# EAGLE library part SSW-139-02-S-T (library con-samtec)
THROUGH-HOLE .025" SQ POST SOCKET Source: Samtec SSW.pdf
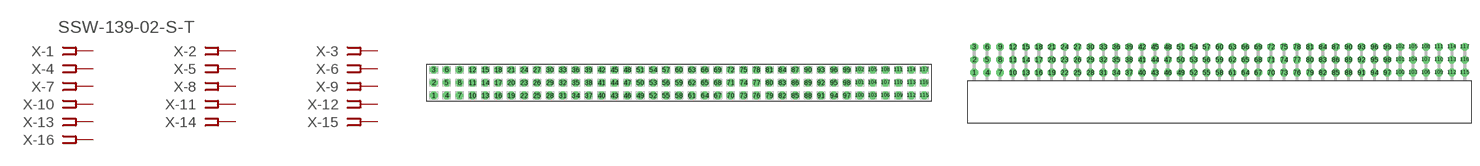
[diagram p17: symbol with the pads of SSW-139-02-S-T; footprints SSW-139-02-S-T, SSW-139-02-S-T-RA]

Designator prefix X; gates -1=FPINV -2=FPIN -3=FPIN -4=FPIN -5=FPIN -6=FPIN -7=FPIN -8=FPIN -9=FPIN -10=FPIN -11=FPIN -12=FPIN -13=FPIN -14=FPIN -15=FPIN -16=FPIN -17=FPIN -18=FPIN -19=FPIN -20=FPIN -21=FPIN -22=FPIN -23=FPIN -24=FPIN -25=FPIN -26=FPIN -27=FPIN -28=FPIN -29=FPIN -30=FPIN -31=FPIN -32=FPIN -33=FPIN -34=FPIN -35=FPIN -36=FPIN -37=FPIN -38=FPIN -39=FPIN -40=FPIN -41=FPIN -42=FPIN -43=FPIN -44=FPIN -45=FPIN -46=FPIN -47=FPIN -48=FPIN -49=FPIN -50=FPIN -51=FPIN -52=FPIN -53=FPIN -54=FPIN -55=FPIN -56=FPIN -57=FPIN -58=FPIN -59=FPIN -60=FPIN -61=FPIN -62=FPIN -63=FPIN -64=FPIN -65=FPIN -66=FPIN -67=FPIN -68=FPIN -69=FPIN -70=FPIN -71=FPIN -72=FPIN -73=FPIN -74=FPIN -75=FPIN -76=FPIN -77=FPIN -78=FPIN -79=FPIN -80=FPIN -81=FPIN -82=FPIN -83=FPIN -84=FPIN -85=FPIN -86=FPIN -87=FPIN -88=FPIN -89=FPIN -90=FPIN -91=FPIN -92=FPIN -93=FPIN -94=FPIN -95=FPIN -96=FPIN -97=FPIN -98=FPIN -99=FPIN -100=FPIN -101=FPIN -102=FPIN -103=FPIN -104=FPIN -105=FPIN -106=FPIN -107=FPIN -108=FPIN -109=FPIN -110=FPIN -111=FPIN -112=FPIN -113=FPIN -114=FPIN -115=FPIN -116=FPIN -117=FPIN

## SSW-139-02-S-T (OC_FARNELL: unknown; OC_NEWARK: unknown)  [SSW-139-02-S-T]
1  -1:1  pas
2  -2:1  pas
3  -3:1  pas
4  -4:1  pas
5  -5:1  pas
6  -6:1  pas
7  -7:1  pas
8  -8:1  pas
9  -9:1  pas
10  -10:1  pas
11  -11:1  pas
12  -12:1  pas
13  -13:1  pas
14  -14:1  pas
15  -15:1  pas
16  -16:1  pas
17  -17:1  pas
18  -18:1  pas
19  -19:1  pas
20  -20:1  pas
21  -21:1  pas
22  -22:1  pas
23  -23:1  pas
24  -24:1  pas
25  -25:1  pas
26  -26:1  pas
27  -27:1  pas
28  -28:1  pas
29  -29:1  pas
30  -30:1  pas
31  -31:1  pas
32  -32:1  pas
33  -33:1  pas
34  -34:1  pas
35  -35:1  pas
36  -36:1  pas
37  -37:1  pas
38  -38:1  pas
39  -39:1  pas
40  -40:1  pas
41  -41:1  pas
42  -42:1  pas
43  -43:1  pas
44  -44:1  pas
45  -45:1  pas
46  -46:1  pas
47  -47:1  pas
48  -48:1  pas
49  -49:1  pas
50  -50:1  pas
51  -51:1  pas
52  -52:1  pas
53  -53:1  pas
54  -54:1  pas
55  -55:1  pas
56  -56:1  pas
57  -57:1  pas
58  -58:1  pas
59  -59:1  pas
60  -60:1  pas
61  -61:1  pas
62  -62:1  pas
63  -63:1  pas
64  -64:1  pas
65  -65:1  pas
66  -66:1  pas
67  -67:1  pas
68  -68:1  pas
69  -69:1  pas
70  -70:1  pas
71  -71:1  pas
72  -72:1  pas
73  -73:1  pas
74  -74:1  pas
75  -75:1  pas
76  -76:1  pas
77  -77:1  pas
78  -78:1  pas
79  -79:1  pas
80  -80:1  pas
81  -81:1  pas
82  -82:1  pas
83  -83:1  pas
84  -84:1  pas
85  -85:1  pas
86  -86:1  pas
87  -87:1  pas
88  -88:1  pas
89  -89:1  pas
90  -90:1  pas
91  -91:1  pas
92  -92:1  pas
93  -93:1  pas
94  -94:1  pas
95  -95:1  pas
96  -96:1  pas
97  -97:1  pas
98  -98:1  pas
99  -99:1  pas
100  -100:1  pas
101  -101:1  pas
102  -102:1  pas
103  -103:1  pas
104  -104:1  pas
105  -105:1  pas
106  -106:1  pas
107  -107:1  pas
108  -108:1  pas
109  -109:1  pas
110  -110:1  pas
111  -111:1  pas
112  -112:1  pas
113  -113:1  pas
114  -114:1  pas
115  -115:1  pas
116  -116:1  pas
117  -117:1  pas

## SSW-139-02-S-TRA (MPN: SSW-139-02-S-T-RA; OC_FARNELL: unknown; OC_NEWARK: 83P1295)  [SSW-139-02-S-T-RA]
Pads as for SSW-139-02-S-T

## Footprint SSW-139-02-S-T (pad centres in mm)
THROUGH-HOLE .025" SQ POST SOCKET Source: Samtec SSW.pdf
drill 1 pad 1.5 octagon: 1 -48.26,-2.54; 2 -48.26,0; 3 -48.26,2.54; 4 -45.72,-2.54; 5 -45.72,0; 6 -45.72,2.54; 7 -43.18,-2.54; 8 -43.18,0; 9 -43.18,2.54; 10 -40.64,-2.54; 11 -40.64,0; 12 -40.64,2.54; 13 -38.1,-2.54; 14 -38.1,0; 15 -38.1,2.54; 16 -35.56,-2.54; 17 -35.56,0; 18 -35.56,2.54; 19 -33.02,-2.54; 20 -33.02,0; 21 -33.02,2.54; 22 -30.48,-2.54; 23 -30.48,0; 24 -30.48,2.54; 25 -27.94,-2.54; 26 -27.94,0; 27 -27.94,2.54; 28 -25.4,-2.54; 29 -25.4,0; 30 -25.4,2.54; 31 -22.86,-2.54; 32 -22.86,0; 33 -22.86,2.54; 34 -20.32,-2.54; 35 -20.32,0; 36 -20.32,2.54; 37 -17.78,-2.54; 38 -17.78,0; 39 -17.78,2.54; 40 -15.24,-2.54; 41 -15.24,0; 42 -15.24,2.54; 43 -12.7,-2.54; 44 -12.7,0; 45 -12.7,2.54; 46 -10.16,-2.54; 47 -10.16,0; 48 -10.16,2.54; 49 -7.62,-2.54; 50 -7.62,0; 51 -7.62,2.54; 52 -5.08,-2.54; 53 -5.08,0; 54 -5.08,2.54; 55 -2.54,-2.54; 56 -2.54,0; 57 -2.54,2.54; 58 0,-2.54; 59 0,0; 60 0,2.54; 61 2.54,-2.54; 62 2.54,0; 63 2.54,2.54; 64 5.08,-2.54; 65 5.08,0; 66 5.08,2.54; 67 7.62,-2.54; 68 7.62,0; 69 7.62,2.54; 70 10.16,-2.54; 71 10.16,0; 72 10.16,2.54; 73 12.7,-2.54; 74 12.7,0; 75 12.7,2.54; 76 15.24,-2.54; 77 15.24,0; 78 15.24,2.54; 79 17.78,-2.54; 80 17.78,0; 81 17.78,2.54; 82 20.32,-2.54; 83 20.32,0; 84 20.32,2.54; 85 22.86,-2.54; 86 22.86,0; 87 22.86,2.54; 88 25.4,-2.54; 89 25.4,0; 90 25.4,2.54; 91 27.94,-2.54; 92 27.94,0; 93 27.94,2.54; 94 30.48,-2.54; 95 30.48,0; 96 30.48,2.54; 97 33.02,-2.54; 98 33.02,0; 99 33.02,2.54; 100 35.56,-2.54; 101 35.56,0; 102 35.56,2.54; 103 38.1,-2.54; 104 38.1,0; 105 38.1,2.54; 106 40.64,-2.54; 107 40.64,0; 108 40.64,2.54; 109 43.18,-2.54; 110 43.18,0; 111 43.18,2.54; 112 45.72,-2.54; 113 45.72,0; 114 45.72,2.54; 115 48.26,-2.54; 116 48.26,0; 117 48.26,2.54

## Footprint SSW-139-02-S-T-RA (pad centres in mm)
THROUGH-HOLE .025" SQ POST SOCKET Source: Samtec SSW.pdf
drill 1 pad 1.5 octagon: 1 -48.26,1.524; 2 -48.26,4.064; 3 -48.26,6.604; 4 -45.72,1.524; 5 -45.72,4.064; 6 -45.72,6.604; 7 -43.18,1.524; 8 -43.18,4.064; 9 -43.18,6.604; 10 -40.64,1.524; 11 -40.64,4.064; 12 -40.64,6.604; 13 -38.1,1.524; 14 -38.1,4.064; 15 -38.1,6.604; 16 -35.56,1.524; 17 -35.56,4.064; 18 -35.56,6.604; 19 -33.02,1.524; 20 -33.02,4.064; 21 -33.02,6.604; 22 -30.48,1.524; 23 -30.48,4.064; 24 -30.48,6.604; 25 -27.94,1.524; 26 -27.94,4.064; 27 -27.94,6.604; 28 -25.4,1.524; 29 -25.4,4.064; 30 -25.4,6.604; 31 -22.86,1.524; 32 -22.86,4.064; 33 -22.86,6.604; 34 -20.32,1.524; 35 -20.32,4.064; 36 -20.32,6.604; 37 -17.78,1.524; 38 -17.78,4.064; 39 -17.78,6.604; 40 -15.24,1.524; 41 -15.24,4.064; 42 -15.24,6.604; 43 -12.7,1.524; 44 -12.7,4.064; 45 -12.7,6.604; 46 -10.16,1.524; 47 -10.16,4.064; 48 -10.16,6.604; 49 -7.62,1.524; 50 -7.62,4.064; 51 -7.62,6.604; 52 -5.08,1.524; 53 -5.08,4.064; 54 -5.08,6.604; 55 -2.54,1.524; 56 -2.54,4.064; 57 -2.54,6.604; 58 0,1.524; 59 0,4.064; 60 0,6.604; 61 2.54,1.524; 62 2.54,4.064; 63 2.54,6.604; 64 5.08,1.524; 65 5.08,4.064; 66 5.08,6.604; 67 7.62,1.524; 68 7.62,4.064; 69 7.62,6.604; 70 10.16,1.524; 71 10.16,4.064; 72 10.16,6.604; 73 12.7,1.524; 74 12.7,4.064; 75 12.7,6.604; 76 15.24,1.524; 77 15.24,4.064; 78 15.24,6.604; 79 17.78,1.524; 80 17.78,4.064; 81 17.78,6.604; 82 20.32,1.524; 83 20.32,4.064; 84 20.32,6.604; 85 22.86,1.524; 86 22.86,4.064; 87 22.86,6.604; 88 25.4,1.524; 89 25.4,4.064; 90 25.4,6.604; 91 27.94,1.524; 92 27.94,4.064; 93 27.94,6.604; 94 30.48,1.524; 95 30.48,4.064; 96 30.48,6.604; 97 33.02,1.524; 98 33.02,4.064; 99 33.02,6.604; 100 35.56,1.524; 101 35.56,4.064; 102 35.56,6.604; 103 38.1,1.524; 104 38.1,4.064; 105 38.1,6.604; 106 40.64,1.524; 107 40.64,4.064; 108 40.64,6.604; 109 43.18,1.524; 110 43.18,4.064; 111 43.18,6.604; 112 45.72,1.524; 113 45.72,4.064; 114 45.72,6.604; 115 48.26,1.524; 116 48.26,4.064; 117 48.26,6.604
